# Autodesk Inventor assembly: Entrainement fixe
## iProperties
Author: Flavien MARTY
Shininess: 21.0
PropertySet Name: _Private Model Information
Created: 2001-10
Part Number: Entrainement fixe
Document SubType Name: Assemblage
Designer: Flavien MARTY
Control State: 0
Master: False
Checked Out: False
PropertySet Name: Design Tracking Control
Density: 0.0
Volumn: 0.0
Area: 0.0
PropertySet Name: Model Information
